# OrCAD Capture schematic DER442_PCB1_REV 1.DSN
size D; title: DER 442_30W Isolated LED Driver, LLO, 1-10V dimming; rev: A; note: Opp; note: Applications Engineering
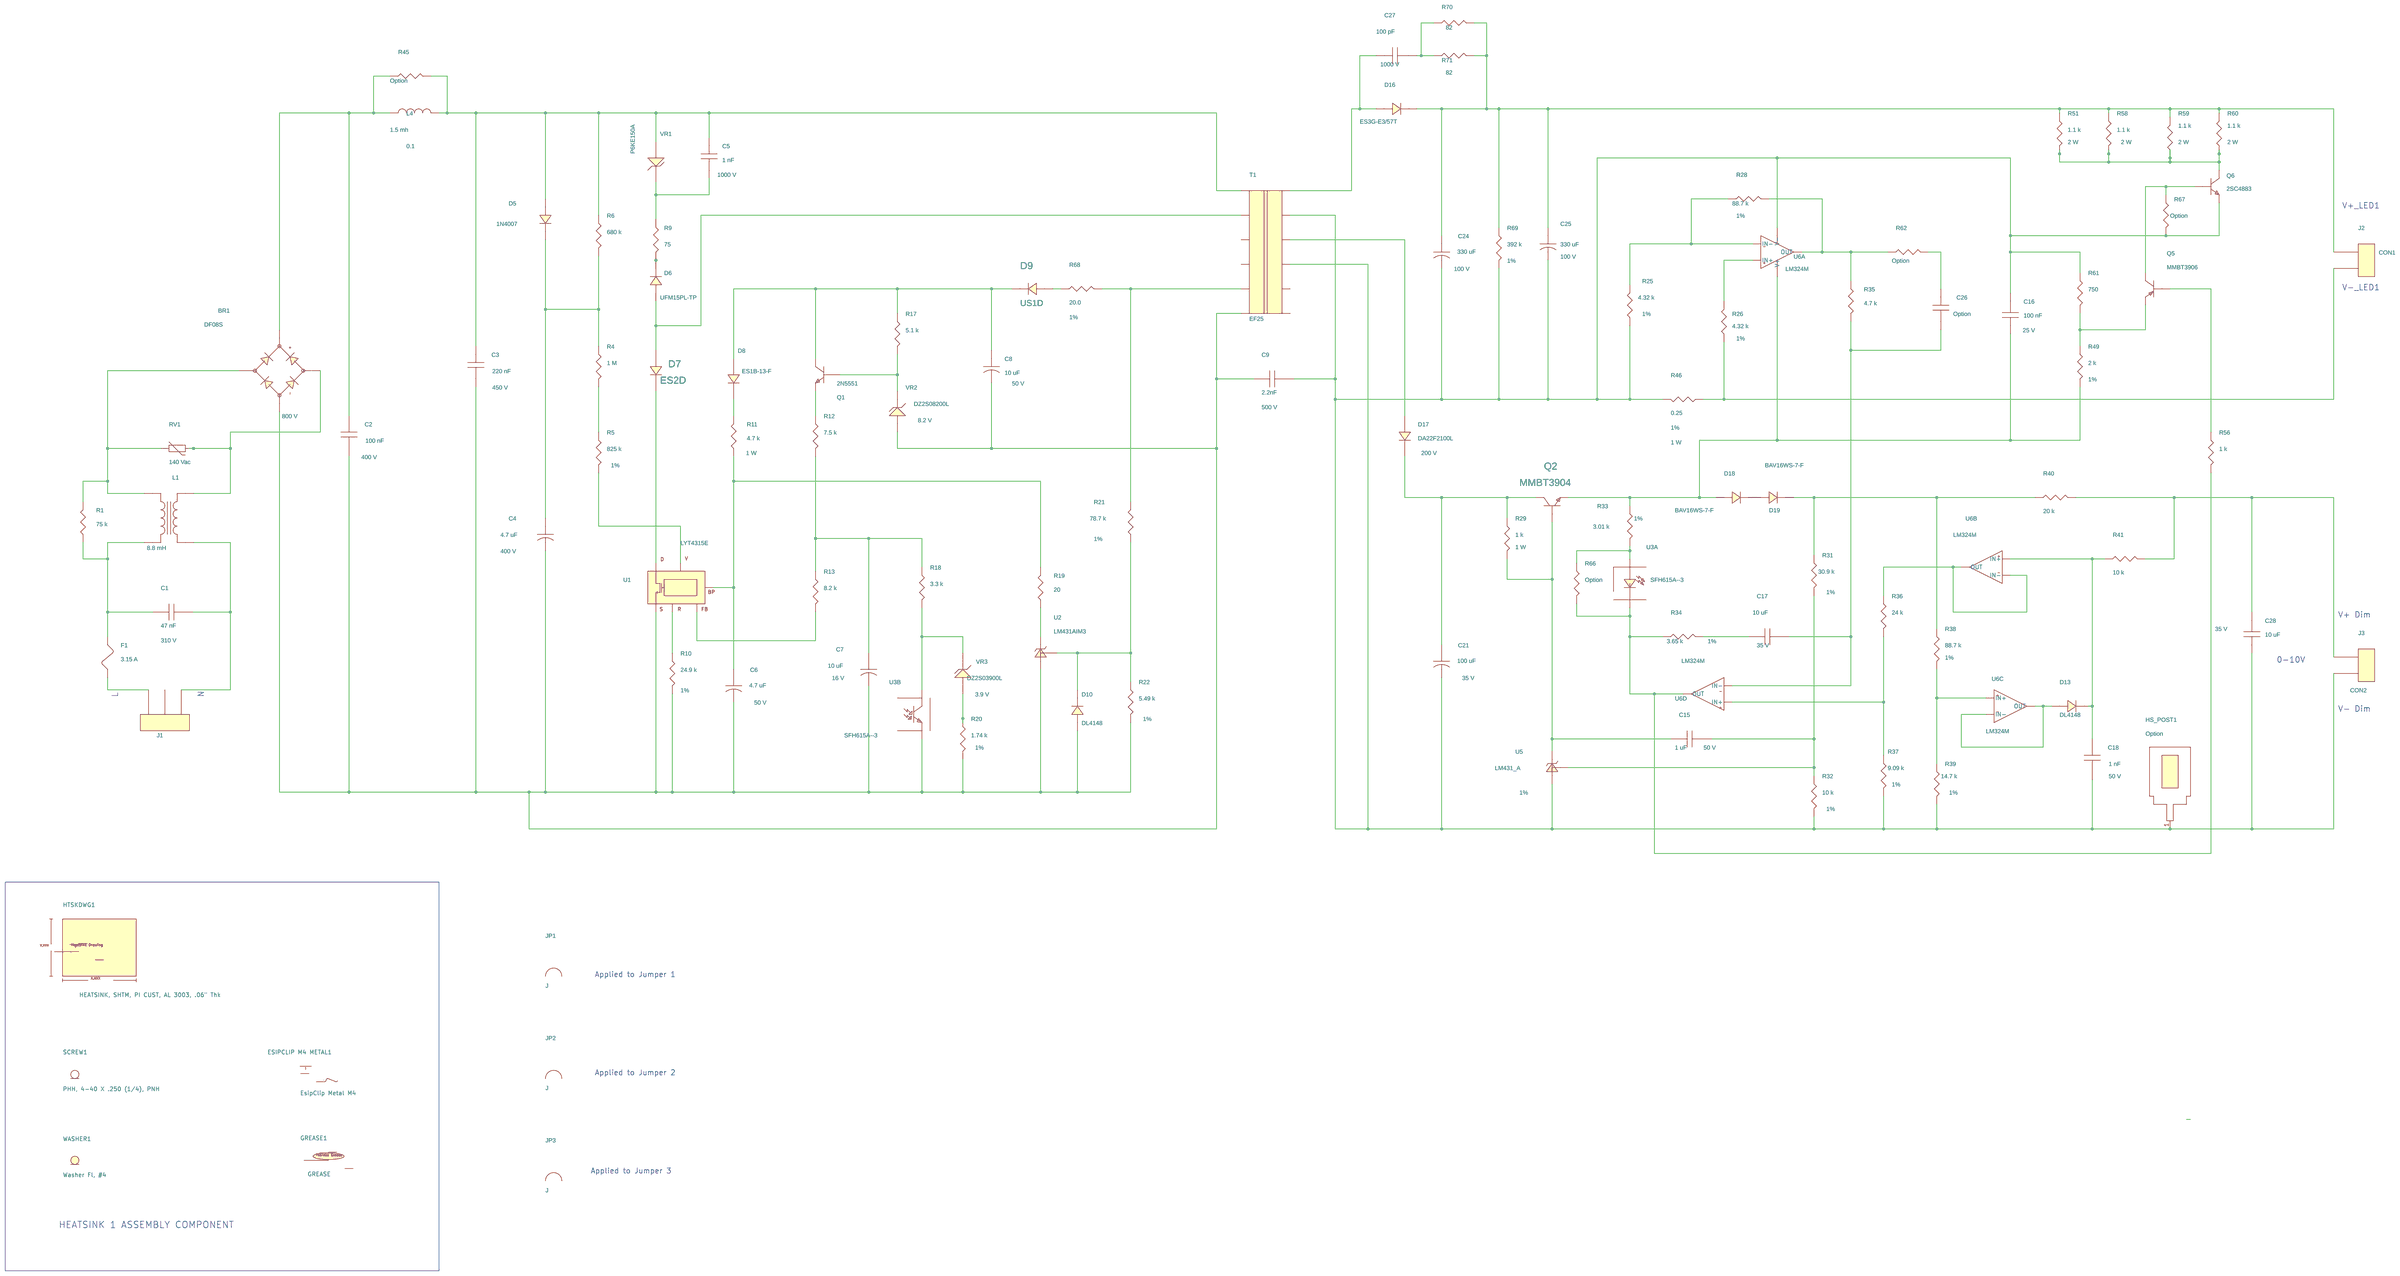
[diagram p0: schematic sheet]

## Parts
BR1  DF08S  [pismddfs]
C1  47 nF  [PI_NP395X200LS300D040]
C2  100 nF  [pinpcaprad500x260400040]
C3  220 nF  [pi_np_cap_rad470x220ls400d40]
C4  4.7 uF  [pipolcapclyd320ls140030]
C5  1 nF  [pismc0805]
C6  4.7 uF  [pipolcapclyd200ls80030]
C7  10 uF  [pipolcapclyd200ls80030]
C8  10 uF  [pipolcapclyd200ls80030]
C9  2.2nF  [pi_np475x200ls395d040]
C15  1 uF  [pismc0805]
C16  100 nF  [pismc0603]
C17  10 uF  [pismc0805]
C18  1 nF  [pismc0805]
C21  100 uF  [pipolcapcyld250ls100030]
C24  330 uF  [pipolcapclyd500ls200040]
C25  330 uF  [pipolcapclyd500ls200040]
C26  Option  [pismc1206]
C27  100 pF  [pismc0805]
C28  10 uF  [pismc0805]
D5  1N4007  [pidv200x110x040do41]
D6  UFM15PL-TP  [pi_sm_sod-123_12]
D7  ES2D  [pismdo214aa12]
D8  ES1B-13-F  [pismdo214ac12]
D9  US1D  [pismdsma]
D10  DL4148  [pismdminimelf]
D13  DL4148  [pismdminimelf]
D16  ES3G-E3/57T  [pismdo214ab12]
D17  DA22F2100L  [pi_sm_sod-123_12]
D18  BAV16WS-7-F  [pismsod323]
D19  BAV16WS-7-F  [pismsod323]
ESIPCLIP M4 METAL1  EsipClip Metal M4
F1  3.15 A  [pi_rst_microfuse]
GREASE1  GREASE
HS_POST1  Option  [pi_hsk_post]
HTSKDWG1  HEATSINK, SHTM, PI CUST, AL 3003, .06" Thk
J1  TERMINAL BLOCK  [pi_term_block_3pin]
J2  CON1  [pi_hdr_2pin_phoenix_196ls]
J3  CON2  [pi_hdr_2pin_phoenix_196ls]
JP1  J  [pi_jumper400]
JP2  J  [pi_jumper200]
JP3  J  [pi_jumper400]
L1  8.8 mH  [piind4p710x590ls512x055]
L4  1.5 mh  [pi_choke_710hx450ls290d046]
Q1  2N5551  [PITO92R100]
Q2  MMBT3904  [pismsot23132]
Q5  MMBT3906  [pismsot23132]
Q6  2SC4883  [pi_to220F]
R1  75 k  [pismr1206]
R4  1 M  [pismr1206]
R5  825 k  [pismr1206]
R6  680 k  [pi14wvresd100ls100d030]
R9  75  [pismr1206]
R10  24.9 k  [pismr1206]
R11  4.7 k  [pi1wresd200ls725d040]
R12  7.5 k  [pismr0805]
R13  8.2 k  [pismr0805]
R17  5.1 k  [pismr1206]
R18  3.3 k  [pi14wvresd100ls100d030]
R19  20  [pismr1206]
R20  1.74 k  [pismr0805]
R21  78.7 k  [pismr1206]
R22  5.49 k  [pismr0805]
R25  4.32 k  [pismr0603]
R26  4.32 k  [pismr0603]
R28  88.7 k  [pismr0603]
R29  1 k  [pi1wresd200ls725d040]
R31  30.9 k  [pismr0603]
R32  10 k  [pismr0603]
R33  3.01 k  [pismr1206]
R34  3.65 k  [pismr0603]
R35  4.7 k  [pismr1206]
R36  24 k  [pi14wvresd100ls100d030]
R37  9.09 k  [pismr0603]
R38  88.7 k  [pismr0603]
R39  14.7 k  [pismr0603]
R40  20 k  [pi14wvresd100ls100d030]
R41  10 k  [pismr0603]
R45  Option  [pismr1206]
R46  0.25  [pi1wresd200ls500d040]
R49  2 k  [pi14wvresd100ls100d030]
R51  1.1 k  [pi2wresd200ls725d040]
R56  1 k  [pismr0603]
R58  1.1 k  [pi2wresd200ls725d040]
R59  1.1 k  [pi2wresd200ls725d040]
R60  1.1 k  [pi2wresd200ls725d040]
R61  750  [pismr0805]
R62  Option  [pismr0603]
R66  Option  [pismr0603]
R67  Option  [pismr0603]
R68  20.0  [pismr0805]
R69  392 k  [pismr1206]
R70  82  [pismr1206]
R71  82  [pismr1206]
RV1  140 Vac  [pinpcaprad370x156250040]
SCREW1  PHH, 4-40 X .250 (1/4), PNH
T1  EF25  [pi_bobbin_ef25_h_12p]
U1  LYT4315E  [piicesip76th]
U2  LM431AIM3  [pismsot23123]
U3  SFH615A--3  [pi_dip4]  (sections A,B)
U5  LM431_A  [PI_TL431CLP]
U6  LM324M  [pisog05014wb300l400]  (sections A,B,C,D)
VR1  P6KE150A  [pidv200x140x050do15do204ac]
VR2  DZ2S08200L  [pi_sm_d_ssmini2p]
VR3  DZ2S03900L  [pi_sm_d_ssmini2p]
WASHER1  Washer Fl, #4

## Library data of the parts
BR1 = DIODE_BRIDGE_+-~~: Disp_Voltage: 800 V; Part Number: 15-00730-00
C1 = CAP_NP: Disp_Voltage: 310 V; Part Number: 20-01115-00; Voltage: 310 V
C2 = CAP_NP: ALT_SYMBOLS: pinpcaprad500x260400040h; Disp_Voltage: 400 V; FPLIST: pinpcaprad500x260400040,pinpcaprad500x260400040h; Part Number: 20-00368-00; Voltage: 400 V
C3 = CAP_NP: Disp_Voltage: 450 V; Part Number: 20-08691-00; Voltage: 450 V
C4 = CAP_POL: ALT_SYMBOLS: pipolcapclyd320ls140030h; Disp_Voltage: 400 V; FPLIST: pipolcapclyd320ls140030,pipolcapclyd320ls140030h; PCB Editor PCBFP: pipolcapcyld250ls100030; Part Number: 20-00428-00; Tol: 20; Voltage: 400 V
C5 = CAP_NP: Disp_Voltage: 1000 V; Part Number: 20-00675-00; Tol: 10; Voltage: 1000 V
C6 = CAP_POL: ALT_SYMBOLS: pipolcapclyd200ls80030h; Disp_Voltage: 50 V; FPLIST: pipolcapclyd200ls80030,pipolcapclyd200ls80030h; Part Number: 20-00442-00; Voltage: 50 V
C7 = CAP_POL: Disp_Voltage: 16 V; Part Number: 20-00649-00; Voltage: 16 V
C8 = CAP_POL: Disp_Voltage: 50 V; PCB Editor PCBFP: pipolcapcyld250ls100030; Part Number: 20-00443-00; Tol: 20; Voltage: 50 V
C9 = CAP_NP: Disp_Voltage: 500 V; Part Number: 20-00985-00; Voltage: 500 V
C15 = CAP_NP: Disp_Voltage: 50 V; Part Number: 20-01022-00; Voltage: 50 V
C16 = CAP_NP: Disp_Voltage: 25 V; Part Number: 20-01050-00; Voltage: 25 V
C17 C28 = CAP_NP: Disp_Voltage: 35 V; Part Number: 20-08720-00; Voltage: 35 V
C18 = CAP_NP: Disp_Voltage: 50 V; Part Number: 20-08750-00; Voltage: 50 V
C21 = CAP_POL: ALT_SYMBOLS: pipolcapcyld250ls100030h; Disp_Voltage: 35 V; FPLIST: pipolcapcyld250ls100030,pipolcapcyld250ls100030h; Part Number: 20-00437-00; Voltage: 35 V
C24 C25 = CAP_POL: ALT_SYMBOLS: pipolcapclyd500ls2000401000lh; Disp_Voltage: 100 V; FPLIST: pipolcapclyd500ls200040,pipolcapclyd500ls2000401000lh; Part Number: 20-01042-00; Voltage: 100 V
C26 = CAP_NP: Disp_Voltage: 25 V; Part Number: 20-00897-00; Voltage: 25 V
C27 = CAP_NP: Disp_Voltage: 1000 V; Part Number: 20-08675-00; Voltage: 1000 V
D5 = DIODE: ALT_SYMBOLS: pidax475x125040do41,pidv200x110x040do41wbead,pidax390x125040do41; COMPGROUP: 1; FPLIST: pidv200x110x040do41,pidax475x125040do41,pidv200x110x040do41wbead,pidax390x125040do41; Part Number: 15-00623-00
D6 = DIODE: Part Number: 15-00927-00
D7 = DIODE: Part Number: 15-00171-00
D8 = DIODE: Part Number: 15-00316-00
D9 = DIODE: COMPGROUP: 3; Part Number: 15-00492-00
D10 D13 = DIODE: Part Number: 15-01069-00
D16 = DIODE: Part Number: 15-00979-00
D17 = DIODE: Disp_Voltage: 200 V; Part Number: 15-01018-00
D18 D19 = DIODE: Part Number: 15-00850-00
ESIPCLIP M4 METAL1 = EsipClip_Metal_M4: Part Number: 60-00042-00
F1 = FUSE: FPLIST: pi_rst_microfuse,pirstmicrofusehoz; Part Number: 40-00020-00; Voltage: 250 V
GREASE1 = Grease_Therm: Part Number: 60-00035-00
HS_POST1 = HS_POST: Part Number: 60-00051-00
HTSKDWG1 = HtskDwg: Part Number: 61-00184-00
J1 = CON3: Part Number: 35-00175-00
J2 J3 = CON2: Part Number: 35-00153-00
JP1 JP3 = JUMPER_1: Part Number: 65-00043-00
JP2 = JUMPER_1: Part Number: 65-00041-00
L1 = INDUCTOR_4P_NP: Part Number: 30-00391-00
L4 = INDUCTOR: Part Number: 30-00337-00; Tol: 0.1
Q1 = NPN_EBC: ALT_SYMBOLS: PIT092100; FPLIST: PITO92R100,PIT092100; Part Number: 55-00034-00
Q2 = NPN_BEC: Part Number: 55-00048-00
Q5 = PNP_BEC: Part Number: 55-00049-00
Q6 = NPN_BCE: ALT_SYMBOLS: pi_to220F_vf1; FPLIST: pi_to220F,pi_to220F_vf1; Part Number: 55-00115-00
R1 = R: Part Number: 05-01397-00
R4 = R: Part Number: 05-01424-00
R5 = R: Disp_Tol: 1%; Part Number: 05-00473-00
R6 = R: ALT_SYMBOLS: pi14wvresd100ls200d030,pi14wresd100ls400d030,pi14wresd100ls500d030; FPLIST: pi14wvresd100ls100d030,pi14wvresd100ls200d030,pi14wresd100ls400d030,pi14wresd100ls500d030; Part Number: 05-02575-00
R9 = R: Part Number: 05-01325-00
R10 = R: Disp_Tol: 1%; Part Number: 05-00327-00
R11 = R: ALT_SYMBOLS: pi1wvresd120ls200d040,pi1wvresd120ls300d040,pi1wvresd200ls200d040,pi1wvresd200ls300d040,pi1wvresd200ls350d040; Disp_Power: 1 W; FPLIST: pi1wresd200ls725d040,pi1wvresd120ls200d040,pi1wvresd120ls300d040,pi1wvresd200ls200d040,pi1wvresd200ls300d040,pi1wvresd200ls350d040; Part Number: 05-02868-00
R12 = R: Part Number: 05-01540-00
R13 = R: Part Number: 05-01541-00
R17 = R: Part Number: 05-01369-00
R18 = R: ALT_SYMBOLS: pi14wvresd100ls200d030,pi14wresd100ls400d030,pi14wresd100ls500d030; FPLIST: pi14wvresd100ls100d030,pi14wvresd100ls200d030,pi14wresd100ls400d030,pi14wresd100ls500d030; Part Number: 05-02519-00
R19 = R: Part Number: 05-01311-00; Tol: 5%
R20 = R: Disp_Tol: 1%; Part Number: 05-03332-00
R21 = R: Disp_Tol: 1%; Part Number: 05-00375-00; Tol: 5%
R22 = R: Disp_Tol: 1%; Part Number: 05-03377-00
R25 R26 = R: Disp_Tol: 1%; PCB Editor PCBFP: pismr0805; Part Number: 05-01139-00; Tol: 5%
R28 R38 = R: Disp_Tol: 1%; Part Number: 05-03275-00
R29 = R: ALT_SYMBOLS: pi1wvresd120ls200d040,pi1wvresd120ls300d040,pi1wvresd200ls200d040,pi1wvresd200ls300d040,pi1wvresd200ls350d040; Disp_Power: 1 W; FPLIST: pi1wresd200ls725d040,pi1wvresd120ls200d040,pi1wvresd120ls300d040,pi1wvresd200ls200d040,pi1wvresd200ls300d040,pi1wvresd200ls350d040; Part Number: 05-02852-00
R31 = R: Disp_Tol: 1%; Part Number: 05-03231-00
R32 = R: Disp_Tol: 1%; Part Number: 05-03182-00
R33 = R: Disp_Tol: 1%; Part Number: 05-00239-00
R34 = R: Disp_Tol: 1%; Part Number: 05-01132-00
R35 = R: PCB Editor PCBFP: pismr0805; Part Number: 05-01368-00; Tol: 5%
R36 = R: ALT_SYMBOLS: pi14wvresd100ls200d030,pi14wresd100ls400d030,pi14wresd100ls500d030; FPLIST: pi14wvresd100ls100d030,pi14wvresd100ls200d030,pi14wresd100ls400d030,pi14wresd100ls500d030; Part Number: 05-02540-00
R37 = R: Disp_Tol: 1%; Part Number: 05-01170-00
R39 = R: Disp_Tol: 1%; Part Number: 05-03198-00
R40 = R: ALT_SYMBOLS: pi14wvresd100ls200d030,pi14wresd100ls400d030,pi14wresd100ls500d030; FPLIST: pi14wvresd100ls100d030,pi14wvresd100ls200d030,pi14wresd100ls400d030,pi14wresd100ls500d030; Part Number: 05-02538-00
R41 = R: Part Number: 05-01712-00
R45 = R: Part Number: 05-01368-00; Tol: 5%
R46 = R: ALT_SYMBOLS: pi1wvresd200ls200d040; Disp_Power: 1 W; Disp_Tol: 1%; FPLIST: pi1wresd200ls500d040,pi1wvresd200ls200d040; Part Number: 05-03133-00
R49 = R: ALT_SYMBOLS: pi14wvresd100ls200d030,pi14wresd100ls400d030,pi14wresd100ls500d030; Disp_Tol: 1%; FPLIST: pi14wvresd100ls100d030,pi14wvresd100ls200d030,pi14wresd100ls400d030,pi14wresd100ls500d030; Part Number: 05-02005-00
R51 R58-R60 = R: ALT_SYMBOLS: pi2wresd200ls900d040,pi2wvresd200ls300d040,pi2wvresd200ls400d040; Disp_Power: 2 W; FPLIST: pi2wresd200ls725d040,pi2wresd200ls900d040,pi2wvresd200ls300d040,pi2wvresd200ls400d040; Part Number: 05-03005-00
R56 = R: Part Number: 05-01688-00
R61 = R: Part Number: 05-01516-00
R62 = R: Disp_Tol: 1%; Part Number: 05-01124-00
R66 = R: Disp_Tol: 1%; Part Number: 05-01166-00
R67 = R: Part Number: 05-01714-00
R68 = R: Disp_Tol: 1%; Part Number: 05-00521-00
R69 = R: Disp_Tol: 1%; Part Number: 05-00442-00
R70 R71 = R: Part Number: 05-01326-00
RV1 = VARISTOR: Part Number: 85-00001-00
SCREW1 = SCR_4-40: Part Number: 75-00001-00
T1 = BEI30_12P_GENERIC: Part Number: 25-00882-00
U1 = LNK40X_eSIP: Part Number: 10-00642-00
U2 = TL431_SOT-23_CAR: Part Number: 45-00268-00
U3 = OPTO_A_B: Part Number: 53-00006-00
U5 = KA431A_TO92: Disp_Tol: 1%; Part Number: 45-00006-00; Tol: 1%
U6 = LM324: Part Number: 45-00126-00
VR1 = DIODE_ZENER: ALT_SYMBOLS: pidax550x140050do15do204ac; FPLIST: pidv200x140x050do15do204ac,pidax550x140050do15do204ac; Part Number: 15-00619-00
VR2 = DIODE_ZENER: Disp_Voltage: 8.2 V; Part Number: 15-01006-00
VR3 = DIODE_ZENER: Disp_Voltage: 3.9 V; Part Number: 15-01002-00
WASHER1 = WASH_FLAT_4: Part Number: 75-00032-00

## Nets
N3036325: C3.1 C5.1 D5.2 L4.2 R6.1 R45.2 T1.1 VR1.2
N3036377: C7.1 R12.2 R13.1 R18.1
N3036609: C24.1 C25.1 D16.1 J2.1 R51.1 R58.1 R59.2 R60.2 R69.1 R70.2 R71.2
N3036925: R4.2 R5.1
N3037005: D7.1 U1.7(D)
N3037093: D6.2 D7.2 T1.2
N3037213: C4.1 D5.1 R4.1 R6.2
N3037237: BR1.2 C2.2 C3.2 C4.2 C6.2 C7.2 C8.2 C9.1 D10.2 R10.2 R20.2 R22.2 T1.6 U1.5(S) U2.2(A) U3.3(E) VR2.2
N3037245: C6.1 R11.1 R19.1 U1.4(BP)
N3037491: BR1.3 L1.1 RV1.2
N3037573: R10.1 U1.1(R)
N3037677: C9.2 C16.2 C18.2 C21.2 C24.2 C25.2 C28.1 HS_POST1.1 J3.2 Q6.3(EMITTER) R25.2 R32.2 R37.2 R39.2 R46.2 R61.1 R67.2 R69.2 T1.9 T1.11 U5.2(A) U6.11(V-)
N3037713: R33.2 R66.1 U3.1(A)
N3038127: R18.2 U3.4(C) VR3.1
N3038179: C15.1 Q2.1(BASE) R29.2 U5.3(C)
N3038231: R5.2 U1.2(V)
N3038285: C21.1 D17.1 Q2.3(COLLECTOR) R29.1
N3038435: D8.1 R11.2
N3038533: F1.1 J1.1
N3038609: Q1.1(EMITTER) R12.1
N3038711: BR1.4 L1.4 R1.2 RV1.1
N3039958: BR1.1 C2.1 L4.1 R45.1
N3046185: D6.1 R9.2
N3047792: C8.1 D8.2 D9.1 Q1.3(COLLECTOR) R17.1
N3060476: R19.2 U2.1(C)
N3061243: D10.1 R21.2 R22.1 U2.3(VREF)
N3061835: R21.1 R68.2 T1.5
N3064352: C27.1 D16.2 T1.12
N3067766: J2.2 R26.2 R46.1
N3070784: R25.1 R28.1 U6.2(IN-)
N3070798: R28.2 R35.2 R62.1 U6.1(OUT)
N3070937: R34.1 R56.2 R66.2 U3.2(C) U6.14(OUT)
N3070979: C16.1 D18.2 Q2.2(EMITTER) R33.1 R49.2 U6.4(V+)
N3073888: D19.1 R31.1 R38.1 R40.1
N3073903: C15.2 R31.2 R32.1 U5.1(VREF)
N3074477: C17.1 R34.2
N3074493: R36.1 U6.6(IN-) U6.7(OUT)
N3074930: R36.2 R37.1 U6.12(IN+)
N3075106: C17.2 C26.2 R35.1 U6.13(IN-)
N3077075: C28.2 J3.1 R40.2 R41.2
N3077081: C18.1 D13.1 R41.1 U6.5(IN+)
N3083007: D13.2 U6.8(OUT) U6.9(IN-)
N3083089: R38.2 R39.1 U6.10(IN+)
N3109029: C1.1 F1.2 L1.3 R1.1
N3109086: C1.2 J1.3 L1.2
N3119295: C5.2 R9.1 VR1.1
N3151365: D17.2 T1.10
N3165324: R13.2 U1.3(FB)
N3168759: Q1.2(BASE) R17.2 VR2.1
N3178422: R26.1 U6.3(IN+)
N3201252: Q5.2(EMITTER) R49.1 R61.2
N3203116: Q6.2(COLLECTOR) R51.2 R58.2 R59.1 R60.1
N3205512: Q5.3(COLLECTOR) Q6.1(BASE) R67.1
N3220537: C26.1 R62.2
N3225688: D18.1 D19.2
N3249281: D9.2 R68.1
N3253476: Q5.1(BASE) R56.1
N3273823: R20.1 VR3.2
N3286857: C27.2 R70.1 R71.1

Not connected (* = marked no-connect by the designer): J1 2; JP1 1 2; JP2 1 2; JP3 1 2; T1 3 4 7 8

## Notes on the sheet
- V+_LED1
- V-_LED1
- V+ Dim
- 0-10V
- L
- N
- V- Dim
- Applied to Jumper 1
- Applied to Jumper 2
- Applied to Jumper 3
- HEATSINK 1 ASSEMBLY COMPONENT
